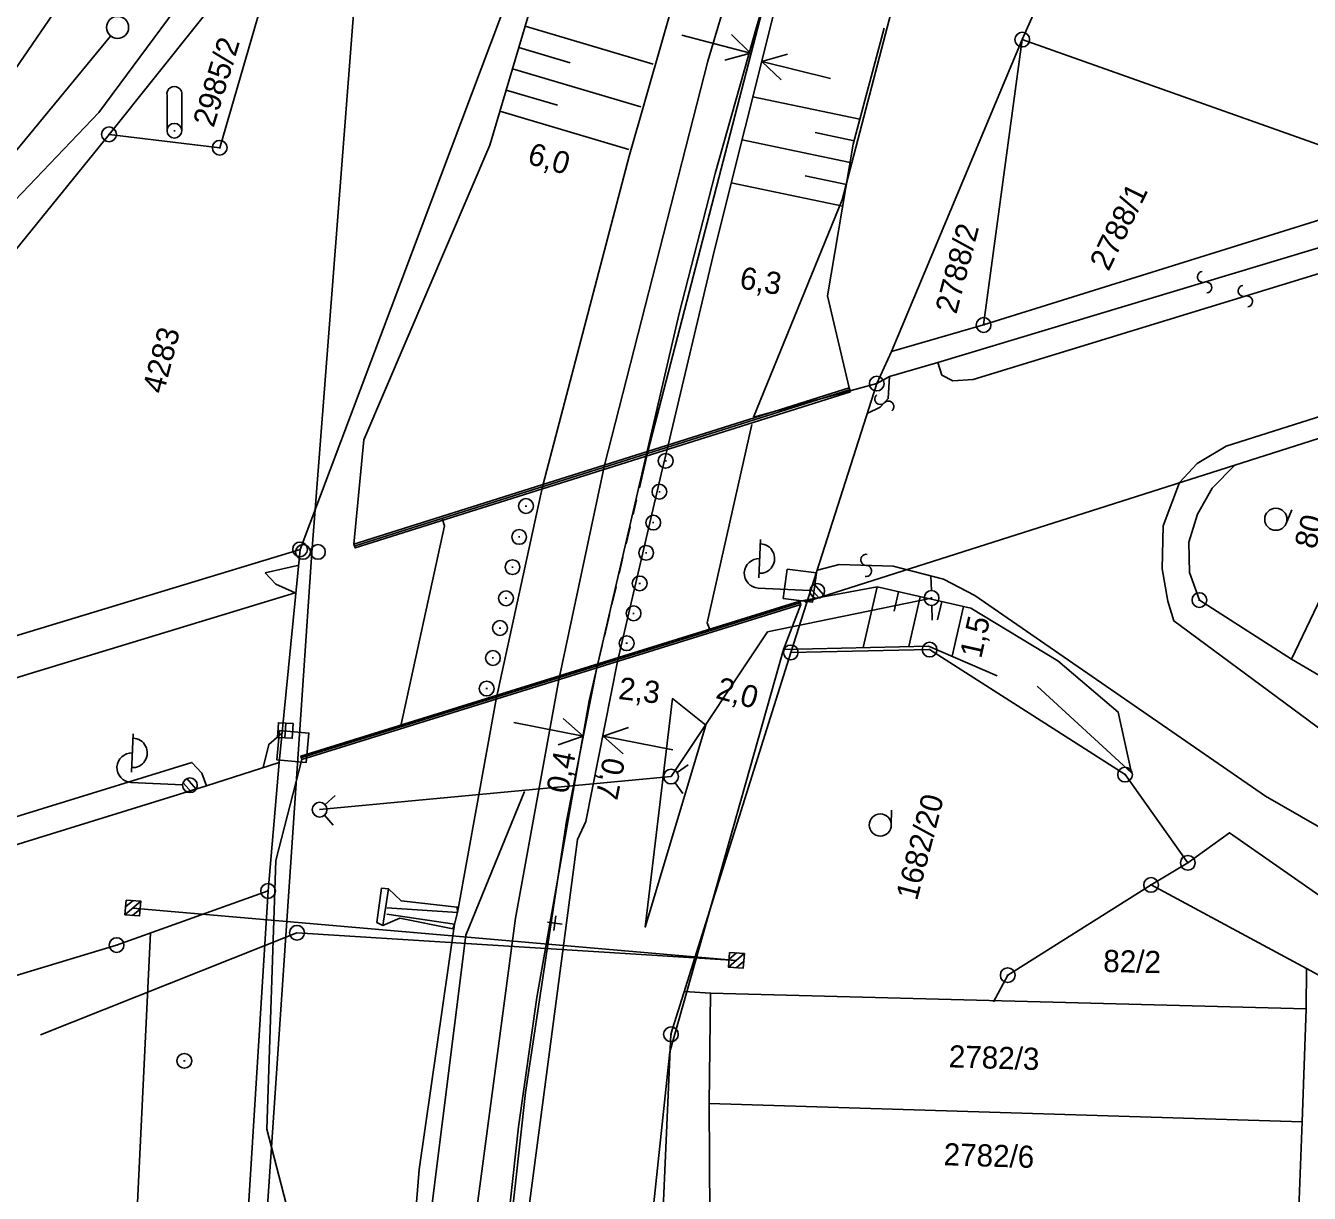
# Model space of a CAD drawing. Extents: x -658910 to -658078, y -1170373 to -1169331.
# Drawn here: x -658449.7 to -658362.8, y -1169995.1 to -1169916 of the extents above; entities that cross this region are included whole.
import ezdxf

# ---------------------------------------------------------------- set-up
doc = ezdxf.new("R2010")
doc.units = 0
for name, color, linetype in [('Vrstva 1', 7, 'Continuous'), ('Vrstva 10', 7, 'Continuous'), ('Vrstva 11', 7, 'Continuous'), ('Vrstva 12', 7, 'Continuous'), ('Vrstva 16', 7, 'Continuous'), ('Vrstva 26', 7, 'Continuous'), ('Vrstva 6', 7, 'Continuous'), ('Vrstva 8', 7, 'Continuous'), ('Vrstva 9', 7, 'Continuous')]:
    doc.layers.add(name, color=color, linetype=linetype)

msp = doc.modelspace()

# ---------------------------------------------------------------- linework, layer by layer
at = {"layer": 'Vrstva 1'}
for p, q in [((-658444.14, -1169923.359), (-658444.04, -1169923.359)), ((-658392.09, -1169940.24), (-658397.91, -1169958.441)), ((-658392.14, -1169940.24), (-658392.04, -1169940.24)), ((-658431.198, -1169951.469), (-658431.098, -1169951.469)), ((-658397.91, -1169958.441), (-658406.031, -1169984.301)), ((-658397.96, -1169958.441), (-658397.86, -1169958.441)), ((-658433.37, -1169974.6), (-658433.27, -1169974.6)), ((-658406.081, -1169984.301), (-658405.981, -1169984.301)), ((-658406.081, -1169984.301), (-658405.981, -1169984.301)), ((-658439.04, -1169986.1), (-658438.94, -1169986.1))]:
    msp.add_line(p, q, dxfattribs=at)
for points in [[(-658535.25, -1169975.531), (-658525.109, -1169972.281), (-658506.949, -1169964.32), (-658490.84, -1169955.289), (-658479.949, -1169947.32), (-658468.961, -1169938.809), (-658451.859, -1169920.99), (-658433.102, -1169893.621), (-658430.531, -1169888.559), (-658387.09, -1169803.74)], [(-658344.84, -1169841.441), (-658351.121, -1169853.93), (-658358.621, -1169867.859), (-658367.191, -1169883.15), (-658382.238, -1169916.941), (-658391.102, -1169938.059), (-658392.09, -1169940.24)], [(-658434.91, -1170000.301), (-658433.32, -1169974.6), (-658432.57, -1169965.9), (-658431.148, -1169951.469), (-658415.48, -1169909.85), (-658422.289, -1169902.77), (-658428.09, -1169905.961)], [(-658428.09, -1169905.961), (-658431.891, -1169908.08), (-658444.09, -1169923.359), (-658456.738, -1169938.969), (-658471.32, -1169950.961), (-658489.809, -1169963.961), (-658501.559, -1169972.781), (-658503.262, -1169973.871), (-658537.41, -1169985.039)], [(-658406.031, -1169984.301), (-658406.73, -1170000.219)]]:
    msp.add_lwpolyline(points, dxfattribs=at)
for centre in [(-658444.09, -1169923.359), (-658392.09, -1169940.24), (-658431.148, -1169951.469), (-658397.91, -1169958.441), (-658433.32, -1169974.6), (-658406.031, -1169984.301), (-658406.031, -1169984.301), (-658438.99, -1169986.1)]:
    msp.add_circle(centre, 0.499, dxfattribs=at)
at = {"layer": 'Vrstva 10'}
for p, q in [((-658401.932, -1169916.59), (-658400.648, -1169917.853)), ((-658398.574, -1169919.671), (-658399.868, -1169918.418)), ((-658406.687, -1169946.365), (-658409.654, -1169959.06)), ((-658414.861, -1169947.84), (-658417.872, -1169961.611)), ((-658413.326, -1169962.925), (-658411.971, -1169964.111)), ((-658409.256, -1169965.302), (-658410.611, -1169964.117)), ((-658412.253, -1169968.539), (-658412.253, -1169968.539))]:
    msp.add_line(p, q, dxfattribs=at)
for points in [[(-658427.5, -1169951.109), (-658426.838, -1169944.052), (-658418.293, -1169924.085), (-658412.835, -1169905.664), (-658412.681, -1169899.985), (-658415.385, -1169894.759), (-658419.286, -1169891.437), (-658421.684, -1169889.994), (-658411.914, -1169872.007), (-658399.264, -1169846.174), (-658387.883, -1169823.23), (-658375.867, -1169800)], [(-658362.5, -1169799.992), (-658377.058, -1169834.921), (-658390.526, -1169867.22), (-658399.748, -1169892.989), (-658408.868, -1169924.83), (-658414.693, -1169947.06)], [(-658405.482, -1169935.482), (-658403.028, -1169926.019), (-658400.233, -1169916.097), (-658397.067, -1169905.522), (-658393.729, -1169895.606), (-658386.751, -1169876.773), (-658379.972, -1169859.803), (-658372.303, -1169841.365), (-658363.947, -1169821.339), (-658354.813, -1169800)], [(-658412.34, -1169868.25), (-658427.96, -1169897.31), (-658435.92, -1169909.92), (-658444.78, -1169921.89), (-658465.67, -1169943.73), (-658479.49, -1169955.1), (-658517.4, -1169976.07), (-658535.91, -1169983.41)], [(-658407.59, -1169944.829), (-658399.692, -1169914.385)], [(-658398.928, -1169914.611), (-658403.084, -1169931.189), (-658406.227, -1169944.399)], [(-658415.91, -1169916.042), (-658407.24, -1169918.611)], [(-658393.958, -1169940.529), (-658395.42, -1169934.288), (-658393.679, -1169924.031), (-658391.595, -1169916.171)], [(-658405.295, -1169916.648), (-658400.648, -1169917.853), (-658402.384, -1169918.332)], [(-658416.336, -1169917.48), (-658412.863, -1169918.509)], [(-658395.213, -1169919.586), (-658399.868, -1169918.418), (-658398.136, -1169917.925)], [(-658416.762, -1169918.918), (-658408.066, -1169921.495)], [(-658417.188, -1169920.357), (-658413.705, -1169921.389)], [(-658393.231, -1169922.343), (-658400.483, -1169920.812)], [(-658417.615, -1169921.795), (-658408.892, -1169924.379)], [(-658393.889, -1169925.27), (-658401.213, -1169923.724)], [(-658393.616, -1169923.794), (-658396.272, -1169923.234)], [(-658394.392, -1169928.23), (-658401.943, -1169926.636)], [(-658394.141, -1169926.75), (-658396.936, -1169926.16)], [(-658411.561, -1169961.716), (-658405.482, -1169935.482)], [(-658408.17, -1169947.291), (-658407.59, -1169944.829)], [(-658406.227, -1169944.399), (-658406.687, -1169946.365)], [(-658414.691, -1169947.06), (-658414.861, -1169947.84)], [(-658408.597, -1169949.106), (-658408.361, -1169948.102)], [(-658409.063, -1169951.083), (-658408.795, -1169949.946)], [(-658409.539, -1169953.108), (-658409.279, -1169952.003)], [(-658410.03, -1169955.189), (-658409.749, -1169953.996)], [(-658397.299, -1169954.984), (-658392.071, -1169954.007), (-658385.715, -1169955.446), (-658379.817, -1169959.014), (-658375.732, -1169962.481), (-658374.838, -1169966.605), (-658381.228, -1169960.722)], [(-658392.071, -1169954.007), (-658393, -1169958.112)], [(-658390.608, -1169954.338), (-658390.905, -1169955.65)], [(-658398.979, -1170189.297), (-658404.442, -1170166.563), (-658409.088, -1170142.051), (-658411.131, -1170114.565), (-658412.045, -1170080.658), (-658411.524, -1170049.223), (-658409, -1170012.742), (-658406.097, -1169985.499), (-658398.397, -1169958.238), (-658397.23, -1169955.206)], [(-658389.145, -1169954.669), (-658389.907, -1169958.04)], [(-658387.682, -1169955), (-658387.976, -1169956.244)], [(-658386.219, -1169955.332), (-658386.982, -1169958.704)], [(-658410.537, -1169957.342), (-658410.194, -1169955.884)], [(-658411.043, -1169959.49), (-658410.689, -1169957.985)], [(-658409.546, -1169958.599), (-658409.654, -1169959.06)], [(-658383.94, -1169960.025), (-658388.584, -1169958.009), (-658398.397, -1169958.238)], [(-658418.194, -1170104.631), (-658419.779, -1170081.152), (-658420.352, -1170064.135), (-658420.207, -1170044.041), (-658419.481, -1170023.386), (-658418.014, -1170007.481), (-658415.888, -1169988.253), (-658413.097, -1169969.872), (-658411.043, -1169959.49)], [(-658409.654, -1169959.06), (-658411.797, -1169969.902)], [(-658417.74, -1169961.007), (-658417.872, -1169961.61)], [(-658417.872, -1169961.611), (-658420.49, -1169976.06), (-658420.7, -1169976.84), (-658423.094, -1169993.471), (-658426.642, -1170037.568), (-658427.061, -1170074.546), (-658424.838, -1170104.223), (-658420.758, -1170135.42), (-658415.909, -1170162.863), (-658409.329, -1170190.564)], [(-658402.315, -1170190.348), (-658407.653, -1170169.771), (-658412.172, -1170148.826), (-658415.215, -1170129.375), (-658417.727, -1170109.679), (-658419.363, -1170090.792), (-658420.432, -1170070.237), (-658420.644, -1170050.611), (-658420.516, -1170040.788), (-658419.395, -1170021.018), (-658418.485, -1170009.912), (-658416.352, -1169990.562), (-658415.125, -1169981.811), (-658411.561, -1169961.716)], [(-658416.68, -1169963.18), (-658411.971, -1169964.111), (-658413.676, -1169964.691)], [(-658405.903, -1169965.048), (-658410.611, -1169964.117), (-658408.906, -1169963.536)], [(-658411.065, -1170191.125), (-658419.009, -1170162.093), (-658425.437, -1170135.194), (-658430.311, -1170105.886), (-658434.217, -1170075.522), (-658434.962, -1170038.771), (-658431.942, -1169996.387), (-658433.406, -1169990.734), (-658432.798, -1169972.528), (-658431.022, -1169965.688)], [(-658408.116, -1170190.76), (-658414.795, -1170162.084), (-658419.971, -1170133.751), (-658423.753, -1170102.123), (-658425.468, -1170076.574), (-658425.385, -1170038.217), (-658422.281, -1169996.311), (-658419.933, -1169977.592), (-658415.95, -1169967.863)], [(-658411.797, -1169969.902), (-658412.351, -1169971.115), (-658417.802, -1170012.345), (-658419.546, -1170050.542), (-658418.979, -1170083.49), (-658416.97, -1170109.116)]]:
    msp.add_lwpolyline(points, dxfattribs=at)
msp.add_lwpolyline([(-658403.656, -1169963.36), (-658405.927, -1169961.569), (-658407.765, -1169977.045)], close=True, dxfattribs=at)
at = {"layer": 'Vrstva 12'}
for p, q in [((-658414.398, -1169976.711), (-658413.407, -1169976.84)), ((-658413.967, -1169977.271), (-658413.838, -1169976.28))]:
    msp.add_line(p, q, dxfattribs=at)
at = {"layer": 'Vrstva 16'}
for p, q in [((-658388.392, -1169954.26), (-658388.417, -1169953.26)), ((-658388.379, -1169954.81), (-658388.381, -1169954.71)), ((-658388.368, -1169955.26), (-658388.343, -1169956.26)), ((-658404.853, -1169966.047), (-658405.613, -1169966.569)), ((-658405.233, -1169968.002), (-658405.741, -1169967.264)), ((-658428.777, -1169968.143), (-658429.463, -1169968.759)), ((-658428.901, -1169970.131), (-658429.499, -1169969.464))]:
    msp.add_line(p, q, dxfattribs=at)
for points in [[(-658398.164, -1169952.8), (-658396.18, -1169953.056), (-658396.436, -1169955.04), (-658398.42, -1169954.784), (-658398.164, -1169952.8)], [(-658432.547, -1169963.725), (-658430.555, -1169963.903), (-658430.733, -1169965.895), (-658432.725, -1169965.717), (-658432.547, -1169963.725)], [(-658432.179, -1169964.229), (-658432.678, -1169964.2), (-658432.62, -1169963.202), (-658431.622, -1169963.26), (-658431.68, -1169964.258), (-658432.179, -1169964.229), (-658432.121, -1169963.231)]]:
    msp.add_lwpolyline(points, dxfattribs=at)
for centre in [(-658388.38, -1169954.76), (-658406.02, -1169966.85), (-658429.83, -1169969.09)]:
    msp.add_circle(centre, 0.5, dxfattribs=at)
at = {"layer": 'Vrstva 26'}
for p, q in [((-658426.51, -1169902.01), (-658430.35, -1169951.67)), ((-658430.35, -1169951.67), (-658433.41, -1169996.588)), ((-658399.49, -1169957.04), (-658388.38, -1169954.76)), ((-658406.02, -1169966.85), (-658399.49, -1169957.04)), ((-658443.016, -1169976.203), (-658441.936, -1169975.296)), ((-658442.97, -1169975.675), (-658442.464, -1169975.251)), ((-658442.491, -1169976.252), (-658441.979, -1169975.822)), ((-658401.601, -1169979.296), (-658442.475, -1169975.752)), ((-658431.36, -1169977.43), (-658448.727, -1169984.333)), ((-658401.601, -1169979.296), (-658431.36, -1169977.43)), ((-658402.096, -1169979.219), (-658401.59, -1169978.795)), ((-658402.142, -1169979.747), (-658401.062, -1169978.84)), ((-658401.617, -1169979.796), (-658401.105, -1169979.366))]:
    msp.add_line(p, q, dxfattribs=at)
for points in [[(-658429.83, -1169969.09), (-658406.02, -1169966.85)], [(-658442.929, -1169975.21), (-658441.933, -1169975.297), (-658442.02, -1169976.293), (-658443.016, -1169976.206), (-658442.929, -1169975.21)], [(-658402.055, -1169978.754), (-658401.059, -1169978.841), (-658401.146, -1169979.837), (-658402.142, -1169979.75), (-658402.055, -1169978.754)]]:
    msp.add_lwpolyline(points, dxfattribs=at)
for points in [[(-658442.929, -1169975.21), (-658441.933, -1169975.297), (-658442.02, -1169976.293), (-658443.016, -1169976.206)], [(-658402.055, -1169978.754), (-658401.059, -1169978.841), (-658401.146, -1169979.837), (-658402.142, -1169979.75)]]:
    msp.add_lwpolyline(points, close=True, dxfattribs=at)
for centre in [(-658430.955, -1169951.639), (-658429.942, -1169951.639), (-658431.36, -1169977.43)]:
    msp.add_circle(centre, 0.5, dxfattribs=at)
at = {"layer": 'Vrstva 6'}
for p, q in [((-658403.57, -1169956.44), (-658400.56, -1169943.01)), ((-658406.44, -1169945.47), (-658406.34, -1169945.47)), ((-658406.86, -1169947.56), (-658406.76, -1169947.56)), ((-658415.9, -1169948.53), (-658415.8, -1169948.53)), ((-658424.33, -1169963.41), (-658421.37, -1169949.86)), ((-658421.37, -1169949.86), (-658421.52, -1169949.37)), ((-658407.28, -1169949.65), (-658407.18, -1169949.65)), ((-658416.36, -1169950.62), (-658416.26, -1169950.62)), ((-658400.081, -1169953.386), (-658399.954, -1169950.789)), ((-658407.76, -1169951.7), (-658407.66, -1169951.7)), ((-658416.81, -1169952.67), (-658416.71, -1169952.67)), ((-658408.2, -1169953.77), (-658408.1, -1169953.77)), ((-658396.619, -1169954.256), (-658400.115, -1169954.085)), ((-658395.997, -1169954.765), (-658396.588, -1169954.113)), ((-658395.695, -1169954.54), (-658396.338, -1169953.831)), ((-658417.25, -1169954.78), (-658417.15, -1169954.78)), ((-658408.61, -1169955.8), (-658408.51, -1169955.8)), ((-658417.66, -1169956.79), (-658417.56, -1169956.79)), ((-658403.4, -1169956.9), (-658403.57, -1169956.44)), ((-658409.08, -1169957.82), (-658408.98, -1169957.82)), ((-658418.14, -1169958.82), (-658418.04, -1169958.82)), ((-658418.56, -1169960.89), (-658418.46, -1169960.89)), ((-658442.571, -1169966.546), (-658442.444, -1169963.949)), ((-658439.109, -1169967.416), (-658442.605, -1169967.245)), ((-658438.487, -1169967.925), (-658439.078, -1169967.273)), ((-658438.185, -1169967.7), (-658438.828, -1169966.991))]:
    msp.add_line(p, q, dxfattribs=at)
for points in [[(-658410.527, -1169945.755), (-658403.539, -1169918.406), (-658401.506, -1169911.538)], [(-658443.997, -1169916.707), (-658452.354, -1169926.822), (-658465.375, -1169939.824), (-658482.656, -1169953.863), (-658495.968, -1169962.556), (-658510.71, -1169970.323), (-658520.257, -1169974.434)], [(-658427.415, -1169951.229), (-658393.963, -1169940.666)], [(-658413.625, -1169960.291), (-658410.527, -1169945.755)], [(-658397.302, -1169955.096), (-658431.041, -1169965.57)], [(-658420.42, -1170005.444), (-658416.553, -1169976.435), (-658413.625, -1169960.291)], [(-658425.27, -1169975.75), (-658420.49, -1169976.06), (-658420.506, -1169975.69), (-658424.31, -1169975.27), (-658425.15, -1169974.46)], [(-658425.55, -1169976.93), (-658424.39, -1169976.45), (-658420.812, -1169977.162), (-658420.7, -1169976.84), (-658425.27, -1169976.16)]]:
    msp.add_lwpolyline(points, dxfattribs=at)
for points in [[(-658393.876, -1169940.789), (-658393.958, -1169940.529), (-658427.5, -1169951.109), (-658427.418, -1169951.369)], [(-658431.022, -1169965.688), (-658431.091, -1169965.466), (-658397.299, -1169954.984), (-658397.23, -1169955.206)], [(-658425.64, -1169974.41), (-658425.15, -1169974.46), (-658425.55, -1169976.93), (-658425.96, -1169976.73)], [(-658425.96, -1169976.73), (-658425.64, -1169974.41), (-658425.15, -1169974.46), (-658425.55, -1169976.93)]]:
    msp.add_lwpolyline(points, close=True, dxfattribs=at)
for centre, radius in [((-658443.512, -1169916.12), 0.75), ((-658406.39, -1169945.47), 0.5), ((-658406.81, -1169947.56), 0.5), ((-658415.85, -1169948.53), 0.5), ((-658407.23, -1169949.65), 0.5), ((-658416.31, -1169950.62), 0.5), ((-658407.71, -1169951.7), 0.5), ((-658416.76, -1169952.67), 0.5), ((-658408.15, -1169953.77), 0.5), ((-658417.2, -1169954.78), 0.5), ((-658396.12, -1169954.28), 0.5), ((-658396.12, -1169954.28), 0.5), ((-658408.56, -1169955.8), 0.5), ((-658417.61, -1169956.79), 0.5), ((-658409.03, -1169957.82), 0.5), ((-658418.09, -1169958.82), 0.5), ((-658418.51, -1169960.89), 0.5), ((-658438.61, -1169967.44), 0.5), ((-658438.61, -1169967.44), 0.5)]:
    msp.add_circle(centre, radius, dxfattribs=at)
for centre, start, end in [((-658400.006, -1169952.088), 266.50473, 87.90987), ((-658400.067, -1169953.086), 87.2073, 267.2073), ((-658442.496, -1169965.248), 266.50473, 87.90987), ((-658442.557, -1169966.246), 87.2073, 267.2073)]:
    msp.add_arc(centre, 1, start, end, dxfattribs=at)
at = {"layer": 'Vrstva 8'}
for p, q in [((-658390.5, -1169912.76), (-658394.43, -1169927.801)), ((-658382.288, -1169916.941), (-658382.188, -1169916.941)), ((-658382.288, -1169916.941), (-658382.188, -1169916.941)), ((-658436.64, -1169924.27), (-658436.54, -1169924.27)), ((-658394.43, -1169927.801), (-658400.449, -1169942.52)), ((-658384.902, -1169936.27), (-658384.802, -1169936.27)), ((-658384.902, -1169936.27), (-658384.802, -1169936.27)), ((-658400.449, -1169942.52), (-658392.09, -1169940.24)), ((-658370.288, -1169954.9), (-658370.188, -1169954.9)), ((-658388.562, -1169958.25), (-658388.462, -1169958.25)), ((-658375.32, -1169966.719), (-658375.22, -1169966.719)), ((-658371.07, -1169972.691), (-658370.97, -1169972.691)), ((-658371.07, -1169972.691), (-658370.97, -1169972.691)), ((-658373.562, -1169974.191), (-658373.462, -1169974.191)), ((-658373.562, -1169974.191), (-658373.462, -1169974.191)), ((-658443.628, -1169978.26), (-658443.528, -1169978.26)), ((-658383.269, -1169980.301), (-658383.169, -1169980.301))]:
    msp.add_line(p, q, dxfattribs=at)
for points in [[(-658387.949, -1169938.809), (-658387.691, -1169939.66), (-658386.93, -1169940.059), (-658385.551, -1169939.961), (-658348.719, -1169928.68), (-658324.219, -1169920.969), (-658320.5, -1169919.58), (-658316.68, -1169917.379), (-658311.98, -1169913.33), (-658308.27, -1169907.711), (-658290.262, -1169872.99), (-658247.48, -1169792.15)], [(-658444.09, -1169923.359), (-658436.59, -1169924.27), (-658431.891, -1169908.08)], [(-658338.93, -1169923.879), (-658351.82, -1169927.941), (-658354.5, -1169926.789), (-658382.238, -1169916.941), (-658384.852, -1169936.27), (-658391.102, -1169938.059)], [(-658354.5, -1169926.789), (-658384.852, -1169936.27)], [(-658391.238, -1169939.76), (-658387.949, -1169938.809), (-658351.82, -1169927.941)], [(-658340.73, -1169935.691), (-658368.422, -1169944.48), (-658370.379, -1169945.641), (-658371.59, -1169946.93)], [(-658392.75, -1169942.27), (-658391.852, -1169941.83), (-658391.309, -1169941.25), (-658391.238, -1169939.76), (-658392.09, -1169940.24)], [(-658396.961, -1169955.051), (-658367.84, -1169945.77), (-658353.949, -1169941.33)], [(-658353.949, -1169941.33), (-658356.602, -1169948.67), (-658359.551, -1169955.66), (-658361.98, -1169954.711), (-658364, -1169958.9)], [(-658304.211, -1169987.02), (-658310.301, -1169984.43), (-658312.949, -1169983.23), (-658319.25, -1169980.49), (-658323.109, -1169978.93), (-658328.238, -1169976.76), (-658332.602, -1169974.84), (-658337.059, -1169972.879), (-658339.289, -1169971.42), (-658345.48, -1169968.67), (-658345.18, -1169967.77), (-658347.699, -1169966.51), (-658352.16, -1169964.82), (-658353.91, -1169964.08), (-658356.148, -1169963.211), (-658361.5, -1169960.359), (-658364, -1169958.9), (-658370.238, -1169954.9), (-658370.91, -1169953.039), (-658370.961, -1169950.98), (-658370.371, -1169949.07), (-658369.371, -1169947.32), (-658367.84, -1169945.77)], [(-658371.59, -1169946.93), (-658372.68, -1169949.871), (-658372.75, -1169952.789), (-658372.371, -1169954.98), (-658371.969, -1169956.309), (-658361.73, -1169963.859), (-658339.211, -1169977.82), (-658329.41, -1169983.051), (-658312.75, -1169988.77), (-658306.32, -1169991.449)], [(-658503.262, -1169973.871), (-658479.34, -1169966.379), (-658456.07, -1169959.039), (-658431.148, -1169951.469)], [(-658431.328, -1169952.551), (-658433.512, -1169953.059), (-658432.789, -1169953.83), (-658431.48, -1169954.41)], [(-658327.23, -1169990.289), (-658365.75, -1169968.17), (-658385.441, -1169954.58), (-658387.578, -1169953.48), (-658390.98, -1169952.609), (-658394.641, -1169952.49), (-658396.102, -1169952.879)], [(-658538.18, -1169987.449), (-658516.57, -1169980.629), (-658498.551, -1169975.039), (-658480.922, -1169969.711), (-658449.5, -1169959.891), (-658431.48, -1169954.41)], [(-658384.18, -1169982.109), (-658383.219, -1169980.301), (-658373.512, -1169974.191), (-658371.02, -1169972.691), (-658375.27, -1169966.719), (-658388.512, -1169958.25), (-658397.91, -1169958.441)], [(-658432.398, -1169963.93), (-658433.27, -1169964.67), (-658433.641, -1169966.23)], [(-658531.1, -1169994.474), (-658495.73, -1169983.559), (-658462.051, -1169973.17), (-658438.48, -1169965.891), (-658437.801, -1169966.629), (-658437.48, -1169967.469)], [(-658432.57, -1169965.9), (-658437.48, -1169967.469), (-658471.859, -1169978.121), (-658499.012, -1169986.42), (-658530.54, -1169996.247)], [(-658371.02, -1169972.691), (-658368.191, -1169970.66), (-658326.559, -1169999.691)], [(-658373.512, -1169974.191), (-658362.988, -1169979.84)], [(-658433.32, -1169974.6), (-658443.578, -1169978.26), (-658483.641, -1169990.371), (-658486.309, -1169991.16), (-658501.789, -1169995.871), (-658500.211, -1170000.27)], [(-658445.899, -1170026.149), (-658443.671, -1170027.088), (-658441.279, -1169977.44)], [(-658356, -1170000.34), (-658355.25, -1169984.07), (-658362.988, -1169979.84), (-658363.012, -1169982.58), (-658363.27, -1169990.23), (-658363.57, -1169997.859), (-658363.98, -1170000.289)], [(-658404, -1170000.27), (-658403.398, -1169996.621), (-658403.449, -1169988.99), (-658403.34, -1169981.51), (-658405.129, -1169981.4)], [(-658403.34, -1169981.51), (-658363.012, -1169982.58)], [(-658403.449, -1169988.99), (-658363.27, -1169990.23)]]:
    msp.add_lwpolyline(points, dxfattribs=at)
for centre in [(-658382.238, -1169916.941), (-658382.238, -1169916.941), (-658436.59, -1169924.27), (-658384.852, -1169936.27), (-658384.852, -1169936.27), (-658370.238, -1169954.9), (-658388.512, -1169958.25), (-658375.27, -1169966.719), (-658371.02, -1169972.691), (-658371.02, -1169972.691), (-658373.512, -1169974.191), (-658373.512, -1169974.191), (-658443.578, -1169978.26), (-658383.219, -1169980.301)]:
    msp.add_circle(centre, 0.499, dxfattribs=at)
for centre, radius, start, end in [((-658369.995, -1169933.009), 0.376, 99.77553, 286.08666), ((-658369.782, -1169933.731), 0.377, 279.09948, 106.7627), ((-658367.235, -1169933.958), 0.376, 100.07245, 286.38358), ((-658367.018, -1169934.68), 0.377, 279.39641, 107.05962), ((-658391.849, -1169941.278), 0.376, 129.89691, 316.20805), ((-658391.303, -1169941.796), 0.377, 309.22087, 136.88409), ((-658392.793, -1169952.174), 0.376, 81.25583, 267.56697), ((-658392.82, -1169952.927), 0.377, 260.57979, 88.24301)]:
    msp.add_arc(centre, radius, start, end, dxfattribs=at)
at = {"layer": 'Vrstva 9'}
for p, q in [((-658440.161, -1169923.117), (-658440.161, -1169920.729)), ((-658439.163, -1169920.725), (-658439.165, -1169923.121)), ((-658439.71, -1169923.117), (-658439.61, -1169923.117)), ((-658439.156, -1169923.124), (-658439.163, -1169923.124)), ((-658364.367, -1169949.715), (-658363.982, -1169948.793)), ((-658391.104, -1169970.135), (-658391.099, -1169969.136))]:
    msp.add_line(p, q, dxfattribs=at)
for centre, radius in [((-658439.66, -1169923.117), 0.501), ((-658365.06, -1169949.426), 0.75), ((-658391.854, -1169970.131), 0.75)]:
    msp.add_circle(centre, radius, dxfattribs=at)
msp.add_arc((-658439.661, -1169920.625), 0.508, 348.60957, 190.47096, dxfattribs=at)

# ---------------------------------------------------------------- texts
at = {"layer": 'Vrstva 11'}
for s, rotation, p in [('6,0', 343.49753, (-658415.825, -1169925.321)), ('6,3', 350.36776, (-658401.44, -1169933.779)), ('1,5', 77.244, (-658385.02, -1169958.908)), ('2,3', 353.22766, (-658409.634, -1169961.593)), ('2,0', 344.22757, (-658403.066, -1169961.516)), ('0,4', 78.81113, (-658413.014, -1169968.06)), ('0,7', 258.81914, (-658410.603, -1169965.481))]:
    msp.add_text(s, height=1.5, rotation=rotation, dxfattribs=at).set_placement(p)
at = {"layer": 'Vrstva 9'}
for s, rotation, p in [('2985/2', 72.9865, (-658437.008, -1169922.954)), ('2788/1', 63.88515, (-658376.392, -1169932.683)), ('2788/2', 75.37005, (-658386.7, -1169935.584)), ('4283', 75.37005, (-658440.398, -1169940.987)), ('80', 75.37005, (-658362.375, -1169951.514)), ('1682/20', 75.37005, (-658389.363, -1169975.304)), ('82/2', 358.71579, (-658376.762, -1169980.08)), ('2782/3', 358.22952, (-658387.23, -1169986.539)), ('2782/6', 358.22952, (-658387.578, -1169993.17))]:
    msp.add_text(s, height=1.5, rotation=rotation, dxfattribs=at).set_placement(p)

doc.saveas('drawing.dxf')
